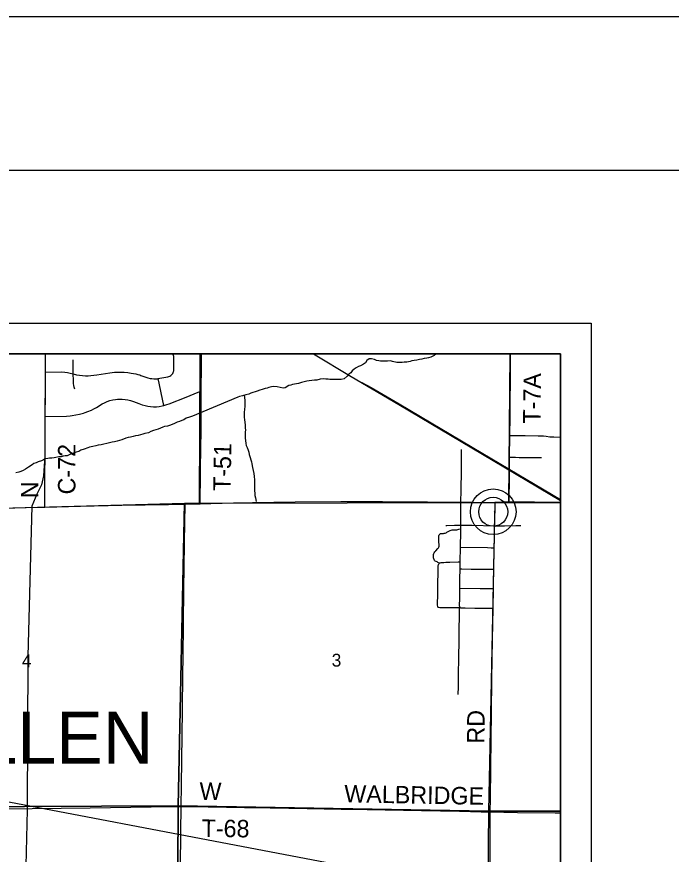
# Model space of a CAD drawing. Extents: x 0 to 34, y 0 to 22.
# Drawn here: x 7.128 to 9.261, y 19.268 to 22 of the extents above; entities that cross this region are included whole.
import ezdxf

# ---------------------------------------------------------------- set-up
doc = ezdxf.new("R2010")
doc.units = 0
for name, color, linetype in [('Default', 7, 'Continuous'), ('GM_X_County_Road', 7, 'Continuous'), ('GM_X_County_Road_Text', 7, 'Continuous'), ('GM_X_Interstate_Route', 7, 'Continuous'), ('GM_X_Major_River', 7, 'Continuous'), ('GM_X_Minor_River', 7, 'Continuous'), ('GM_X_Rail_Line', 7, 'Continuous'), ('GM_X_Section', 7, 'Continuous'), ('GM_X_Section_Text', 7, 'Continuous'), ('GM_X_State_Route', 7, 'Continuous'), ('GM_X_Township_Road', 7, 'Continuous'), ('GM_X_Township_Road_Text', 7, 'Continuous'), ('GM_X_Township_Text', 7, 'Continuous'), ('GM_X_Unincorporated', 7, 'Continuous'), ('GM_X_Unincorporated_Location', 7, 'Continuous'), ('SH_Border', 7, 'Continuous'), ('SH_Cut_Line', 7, 'Continuous'), ('SH_Data', 7, 'Continuous'), ('SH_Text', 7, 'Continuous')]:
    doc.layers.add(name, color=color, linetype=linetype)

msp = doc.modelspace()

# ---------------------------------------------------------------- linework, layer by layer
at = {"layer": 'Default'}
for points in [[(7.7257, 20.9), (6.7117, 20.9), (6.7136, 20.3867), (7.6743, 20.413), (7.7236, 20.4137)], [(8.7361, 20.9), (7.7257, 20.9), (7.7236, 20.4137), (8.6867, 20.4157), (8.7314, 20.4172)], [(8.9, 20.4157), (8.9, 20.9), (8.7361, 20.9), (8.7314, 20.4172)], [(8.9, 19.4085), (8.9, 20.4157), (8.7314, 20.4172), (8.6867, 20.4157), (8.666, 19.4088)], [(8.9, 18.3933), (8.9, 19.4085), (8.666, 19.4088), (8.6554, 18.3927)]]:
    msp.add_lwpolyline(points, close=True, dxfattribs=at)
at = {"layer": 'GM_X_County_Road'}
msp.add_line((7.2211, 20.8407), (7.2213, 20.9), dxfattribs=at)
for points in [[(7.2206, 20.6963), (7.221, 20.8181), (7.2211, 20.8407)], [(7.2196, 20.4008), (7.2195, 20.4853), (7.22, 20.5881), (7.2205, 20.6534), (7.2206, 20.6963)], [(7.6641, 19.424), (7.665, 19.4929), (7.668, 19.7384), (7.6697, 19.8566), (7.6702, 19.9094), (7.6728, 20.1332), (7.6756, 20.3539), (7.6766, 20.4036), (7.6767, 20.4104)], [(6.9678, 19.4166), (6.9849, 19.4166), (7.1776, 19.4172), (7.3674, 19.4198), (7.5661, 19.4229), (7.5971, 19.4234), (7.6537, 19.424), (7.6641, 19.424)], [(7.6615, 19.1928), (7.6618, 19.2257), (7.663, 19.3406), (7.6641, 19.424)]]:
    msp.add_lwpolyline(points, dxfattribs=at)
at = {"layer": 'GM_X_Interstate_Route'}
msp.add_lwpolyline([(8.9, 17.3895), (8.9, 20.9), (4.7088, 20.9), (4.7053, 20.5025), (4.7052, 20.3461), (4.7052, 20.3382), (4.7052, 20.2636), (4.7052, 20.2455), (4.7051, 20.2077), (4.7051, 20.1455), (4.7053, 20.0088), (4.7051, 19.9497), (4.7052, 19.9217), (4.7054, 19.8814), (4.7049, 19.8162), (4.7051, 19.726), (4.7054, 19.4463), (4.7058, 19.4215), (4.706, 19.4081), (4.7064, 19.3593), (4.7066, 19.3437), (4.7069, 19.3065), (4.7068, 19.2692), (4.7066, 19.2071)], dxfattribs=at)
at = {"layer": 'GM_X_Major_River'}
for points in [[(8.4955, 20.9), (8.4953, 20.8999), (8.4884, 20.8954), (8.4778, 20.8893), (8.4702, 20.8871), (8.4641, 20.8864), (8.4554, 20.8853), (8.4482, 20.8834), (8.4406, 20.8819), (8.4315, 20.8797), (8.4235, 20.8782), (8.416, 20.8771), (8.4099, 20.8756), (8.3996, 20.8734), (8.3906, 20.8731), (8.3845, 20.8727), (8.375, 20.8724), (8.3663, 20.8721), (8.3531, 20.8756), (8.3459, 20.8771), (8.3368, 20.8768), (8.3269, 20.8761), (8.3201, 20.8761), (8.314, 20.8765), (8.308, 20.8773), (8.3008, 20.8792), (8.2936, 20.8819), (8.2841, 20.8839), (8.2762, 20.8839), (8.269, 20.8782), (8.2644, 20.8714), (8.2583, 20.8669), (8.248, 20.8613), (8.2416, 20.8587), (8.234, 20.8545), (8.2275, 20.8508), (8.221, 20.8447), (8.2168, 20.8387), (8.2108, 20.8345), (8.2047, 20.8274), (8.1952, 20.8194), (8.1849, 20.8172), (8.1766, 20.8165), (8.1701, 20.8165), (8.1637, 20.8169), (8.1489, 20.817), (8.1429, 20.8174), (8.1353, 20.8178), (8.1281, 20.8186), (8.1167, 20.8175), (8.1061, 20.8149), (8.0985, 20.8146), (8.0902, 20.8139), (8.0807, 20.8128), (8.0739, 20.8113), (8.0648, 20.8091), (8.0557, 20.8072), (8.0458, 20.8042), (8.0397, 20.8031), (8.0333, 20.8017), (8.0272, 20.8002)], [(8.0272, 20.8002), (8.0208, 20.7983), (8.0147, 20.7968), (8.0033, 20.79), (7.9965, 20.7889), (7.9866, 20.7905), (7.9764, 20.7928), (7.9662, 20.794), (7.9582, 20.7929), (7.9499, 20.7907), (7.9438, 20.7888), (7.9374, 20.787), (7.9279, 20.784), (7.9207, 20.7817), (7.9115, 20.7784), (7.9051, 20.7761), (7.8975, 20.7739), (7.8907, 20.7716), (7.8846, 20.7694), (7.8744, 20.7664), (7.8641, 20.7638), (7.8539, 20.7608), (7.8482, 20.7593)], [(7.8482, 20.7593), (7.7012, 20.6971), (7.6906, 20.6941), (7.6804, 20.6904), (7.6724, 20.6851), (7.6663, 20.6832), (7.6583, 20.6798), (7.6511, 20.6776), (7.6397, 20.6716), (7.6257, 20.6663), (7.6192, 20.6645), (7.6098, 20.663), (7.6037, 20.6611), (7.5961, 20.6578), (7.5885, 20.6548), (7.5809, 20.6522), (7.5741, 20.6503), (7.5646, 20.6469), (7.557, 20.6432), (7.5456, 20.6402), (7.5384, 20.6379), (7.5312, 20.6361), (7.5232, 20.6342), (7.5149, 20.6331), (7.5073, 20.6313), (7.499, 20.629), (7.4914, 20.6272), (7.4834, 20.6249), (7.4709, 20.6201), (7.4553, 20.616), (7.4466, 20.6134), (7.439, 20.6119), (7.4219, 20.6082), (7.4113, 20.606), (7.4026, 20.6041), (7.3931, 20.6023), (7.3859, 20.6008), (7.3757, 20.5985), (7.3654, 20.5959), (7.3593, 20.5941), (7.3472, 20.5896), (7.3366, 20.5858), (7.3301, 20.5821), (7.321, 20.5795), (7.313, 20.5769), (7.3005, 20.572), (7.2925, 20.5682), (7.2861, 20.5675), (7.2793, 20.5664), (7.2721, 20.5649), (7.2649, 20.5642), (7.2554, 20.5623), (7.2493, 20.5616), (7.2417, 20.5605), (7.2349, 20.5598), (7.2288, 20.5594), (7.2209, 20.5583), (7.2148, 20.555), (7.208, 20.5516), (7.1981, 20.5478), (7.1909, 20.5452), (7.184, 20.5422), (7.1776, 20.5381)], [(7.1776, 20.5381), (7.1666, 20.5302), (7.1567, 20.5245), (7.1483, 20.5204), (7.1411, 20.5162), (7.135, 20.5144), (7.1248, 20.5122)]]:
    msp.add_lwpolyline(points, dxfattribs=at)
at = {"layer": 'GM_X_Minor_River'}
msp.add_lwpolyline([(7.8695, 20.7652), (7.8709, 20.7493), (7.8708, 20.7425), (7.8715, 20.7342), (7.8715, 20.7281), (7.8703, 20.7198), (7.8695, 20.7091), (7.8691, 20.7019), (7.8691, 20.694), (7.8702, 20.6856), (7.8709, 20.678), (7.8723, 20.6681), (7.8727, 20.6594), (7.873, 20.6518), (7.8726, 20.6458), (7.8722, 20.6386), (7.8725, 20.6317), (7.8725, 20.6249), (7.8732, 20.6173), (7.8743, 20.6082), (7.8758, 20.6017), (7.8788, 20.5945), (7.8822, 20.5858), (7.884, 20.5793), (7.8859, 20.5725), (7.8889, 20.5622), (7.8907, 20.5546), (7.8926, 20.5482), (7.8941, 20.5413), (7.8967, 20.5295), (7.8989, 20.52), (7.9007, 20.5102), (7.9018, 20.4999), (7.9025, 20.4889), (7.9025, 20.4821), (7.9028, 20.4756), (7.9024, 20.4688), (7.9024, 20.4612), (7.9027, 20.454), (7.9034, 20.4457), (7.9042, 20.4388), (7.9056, 20.4312), (7.9086, 20.4191)], dxfattribs=at)
at = {"layer": 'GM_X_Rail_Line'}
for points in [[(7.2205, 20.9), (7.2191, 20.567), (7.2148, 20.5028), (7.2089, 20.4736), (7.1929, 20.443), (7.1768, 20.4036), (7.1637, 19.9147), (7.1622, 19.4128), (7.1374, 18.4088), (7.1389, 18.0601), (7.1325, 17.6042)], [(8.0952, 20.9), (8.2181, 20.8268), (8.373, 20.7348), (8.6459, 20.5729), (8.9, 20.4221)], [(8.2524, 20.8064), (8.283, 20.791), (8.3742, 20.7368), (8.6471, 20.5749), (8.9, 20.4248)]]:
    msp.add_lwpolyline(points, dxfattribs=at)
at = {"layer": 'GM_X_Section'}
for points in [[(7.6743, 20.413), (7.6545, 19.4258), (6.6525, 19.4215), (6.6624, 20.3857), (6.7136, 20.3867)], [(7.7236, 20.4137), (8.6867, 20.4157), (8.666, 19.4088), (7.6545, 19.4258), (7.6743, 20.413)], [(7.6545, 19.4258), (7.6481, 18.4165), (6.6382, 18.4059), (6.6525, 19.4215)], [(8.666, 19.4088), (8.6554, 18.3927), (7.6481, 18.4165), (7.6545, 19.4258)]]:
    msp.add_lwpolyline(points, close=True, dxfattribs=at)
at = {"layer": 'GM_X_State_Route'}
for points in [[(7.0328, 20.3951), (7.0479, 20.3956), (7.159, 20.399), (7.2196, 20.4008), (7.3361, 20.4034), (7.4704, 20.4063), (7.6226, 20.4091), (7.6767, 20.4104), (7.7258, 20.4115)], [(7.7258, 20.4115), (7.7606, 20.4123), (7.8345, 20.4139), (7.8965, 20.4153), (8.0358, 20.4178), (8.1841, 20.4186), (8.2528, 20.4184)], [(8.2528, 20.4184), (8.2608, 20.4184), (8.3198, 20.4182), (8.4669, 20.4173), (8.5758, 20.4165), (8.6148, 20.4166), (8.6879, 20.416)], [(8.6879, 20.416), (8.7102, 20.4159), (8.7328, 20.4156)], [(8.7328, 20.4156), (8.7713, 20.4151), (8.9, 20.4145)]]:
    msp.add_lwpolyline(points, dxfattribs=at)
at = {"layer": 'GM_X_Township_Road'}
for p, q in [((7.3122, 20.835), (7.3122, 20.8809)), ((7.6071, 20.7317), (7.589, 20.8195)), ((8.5758, 20.4165), (8.5761, 20.4554)), ((8.5753, 20.33), (8.5754, 20.3416)), ((8.5735, 20.2217), (8.5743, 20.2697)), ((8.683, 20.1977), (8.6845, 20.2677)), ((8.5731, 20.1986), (8.5735, 20.2217)), ((8.5718, 20.1013), (8.5721, 20.1361)), ((8.6807, 20.0705), (8.6817, 20.1347))]:
    msp.add_line(p, q, dxfattribs=at)
for points in [[(7.589, 20.8195), (7.5946, 20.8206), (7.6208, 20.8258), (7.624, 20.8265), (7.6271, 20.8278), (7.6297, 20.8294), (7.6322, 20.8315), (7.6344, 20.8338), (7.6363, 20.8364), (7.6379, 20.8392), (7.6391, 20.8423), (7.6398, 20.8454), (7.6402, 20.8485), (7.6403, 20.886), (7.6401, 20.8889), (7.6397, 20.8922), (7.6389, 20.8953), (7.6379, 20.8984), (7.6372, 20.9)], [(7.7291, 20.7774), (7.7293, 20.7941), (7.7299, 20.8492), (7.7303, 20.9)], [(8.7351, 20.634), (8.7361, 20.6948), (8.736, 20.6988), (8.7375, 20.8581), (8.7376, 20.9)], [(7.2211, 20.8407), (7.2747, 20.8413), (7.2842, 20.8407), (7.2933, 20.8393), (7.3023, 20.8377), (7.3122, 20.835)], [(7.3122, 20.835), (7.3231, 20.8324), (7.3325, 20.8305), (7.3419, 20.8293), (7.3514, 20.8287), (7.3606, 20.8288), (7.3696, 20.8295), (7.3885, 20.8322), (7.4314, 20.8388), (7.4462, 20.8403), (7.4558, 20.8408), (7.4682, 20.8407), (7.4779, 20.8404), (7.4897, 20.8395), (7.5003, 20.8379), (7.5084, 20.8365), (7.516, 20.8349), (7.5228, 20.8332), (7.5285, 20.8315), (7.5324, 20.8302), (7.5556, 20.8222), (7.5622, 20.8205), (7.5678, 20.8195), (7.5747, 20.8188), (7.581, 20.8187), (7.5864, 20.8191), (7.589, 20.8195)], [(7.3169, 20.7854), (7.3152, 20.7914), (7.3139, 20.7976), (7.3131, 20.8038), (7.3127, 20.8132), (7.3122, 20.835)], [(7.6071, 20.7317), (7.6168, 20.7347), (7.6252, 20.7378), (7.68, 20.7596), (7.7191, 20.7753), (7.7221, 20.7764), (7.7243, 20.7769), (7.7267, 20.7772), (7.7291, 20.7774)], [(7.7258, 20.4115), (7.7267, 20.5111), (7.7283, 20.6044), (7.7288, 20.6383), (7.7285, 20.7068), (7.7291, 20.7774)], [(7.2206, 20.6963), (7.2899, 20.6975), (7.3023, 20.6982), (7.3085, 20.699), (7.3207, 20.701), (7.3329, 20.7036), (7.3449, 20.7067), (7.3508, 20.7087), (7.3595, 20.7119), (7.371, 20.7168), (7.3793, 20.7209), (7.3875, 20.7254), (7.406, 20.7368), (7.4143, 20.7411), (7.4228, 20.7448), (7.4316, 20.7478), (7.4407, 20.7501), (7.4498, 20.7518), (7.456, 20.7525), (7.4622, 20.7527), (7.4716, 20.7526), (7.4808, 20.7518), (7.49, 20.7502), (7.4991, 20.748), (7.5079, 20.745), (7.5253, 20.7383), (7.537, 20.7341), (7.5459, 20.7315), (7.5551, 20.7296), (7.5643, 20.7285), (7.5736, 20.7279), (7.5829, 20.728), (7.5922, 20.7289), (7.6014, 20.7304), (7.6071, 20.7317)], [(8.7344, 20.5634), (8.7345, 20.594), (8.7351, 20.634)], [(8.7351, 20.634), (8.7601, 20.6336), (8.7851, 20.6337), (8.8273, 20.6333), (8.8445, 20.6325)], [(8.8445, 20.6325), (8.8538, 20.6314), (8.8659, 20.6299), (8.8791, 20.6295), (8.9, 20.6288)], [(8.5761, 20.4554), (8.5773, 20.5204), (8.578, 20.5637), (8.5781, 20.5885)], [(8.7328, 20.4156), (8.7329, 20.4209), (8.733, 20.4335), (8.7336, 20.4821), (8.7344, 20.5444), (8.7344, 20.5634)], [(8.7344, 20.5634), (8.7535, 20.563), (8.7658, 20.5628), (8.8385, 20.5624)], [(8.5755, 20.3666), (8.5756, 20.3734), (8.5758, 20.4098), (8.5758, 20.4154), (8.5758, 20.4165)], [(8.6857, 20.3399), (8.6861, 20.3534), (8.6863, 20.3616), (8.6874, 20.3996), (8.6878, 20.4126), (8.6879, 20.416)], [(8.6879, 20.416), (8.7102, 20.4159), (8.7328, 20.4156)], [(8.5754, 20.3416), (8.5754, 20.3489), (8.5755, 20.3666)], [(8.5055, 20.2178), (8.5009, 20.2202), (8.4981, 20.2217), (8.4951, 20.223), (8.4921, 20.2245), (8.4899, 20.2266), (8.4881, 20.2291), (8.487, 20.2318), (8.4864, 20.235), (8.486, 20.2387), (8.4861, 20.2426), (8.4864, 20.2456), (8.4875, 20.2489), (8.4887, 20.2516), (8.4903, 20.2541), (8.492, 20.2558), (8.494, 20.2582), (8.5006, 20.2649), (8.5023, 20.2674), (8.5035, 20.2701), (8.5043, 20.273), (8.5046, 20.2761), (8.5045, 20.2792), (8.504, 20.2853), (8.5037, 20.2915), (8.5037, 20.304), (8.504, 20.3072), (8.5048, 20.3102), (8.5066, 20.3126), (8.5092, 20.314), (8.5122, 20.3145), (8.5184, 20.3147), (8.5215, 20.315), (8.5245, 20.3157), (8.5274, 20.3168), (8.5302, 20.3182), (8.5382, 20.3231), (8.541, 20.3244), (8.544, 20.3254), (8.547, 20.326), (8.5501, 20.3263), (8.5595, 20.3266), (8.5626, 20.3268), (8.5657, 20.3273), (8.5687, 20.3282), (8.5753, 20.33)], [(8.5267, 20.3407), (8.5299, 20.3408), (8.5547, 20.341), (8.5754, 20.3416)], [(8.5743, 20.2697), (8.5752, 20.3211), (8.5753, 20.33)], [(8.5754, 20.3416), (8.5842, 20.3418), (8.5939, 20.3418), (8.6125, 20.3411), (8.6857, 20.3399)], [(8.6845, 20.2677), (8.6851, 20.2949), (8.6857, 20.3399)], [(8.6857, 20.3399), (8.7182, 20.3398), (8.7552, 20.3401), (8.7707, 20.3401)], [(8.5743, 20.2697), (8.662, 20.2682), (8.6747, 20.2679), (8.6845, 20.2677)], [(8.5731, 20.0735), (8.5704, 20.0726), (8.5678, 20.072), (8.5652, 20.0716), (8.5627, 20.0714), (8.5336, 20.0719), (8.5272, 20.0719), (8.5221, 20.0719), (8.5133, 20.072), (8.5102, 20.0721), (8.507, 20.0722), (8.5023, 20.0728), (8.5007, 20.0741), (8.5001, 20.0758), (8.4997, 20.0806), (8.4997, 20.084), (8.4998, 20.0925), (8.5002, 20.107), (8.5005, 20.1224), (8.5007, 20.1383), (8.5009, 20.1504), (8.5016, 20.1877), (8.5017, 20.2095), (8.5022, 20.2126), (8.5033, 20.2155), (8.5055, 20.2178)], [(8.5055, 20.2178), (8.5081, 20.2189), (8.5112, 20.2194), (8.5205, 20.2203), (8.5267, 20.2207), (8.5391, 20.2211), (8.5666, 20.2216), (8.5735, 20.2217)], [(8.5721, 20.1361), (8.5725, 20.1652), (8.5731, 20.1986)], [(8.5731, 20.1986), (8.5785, 20.1986), (8.6096, 20.1984), (8.659, 20.1981), (8.683, 20.1977)], [(8.6817, 20.1347), (8.6819, 20.1458), (8.683, 20.1977)], [(8.5721, 20.1361), (8.6382, 20.1353), (8.6484, 20.1352), (8.6718, 20.1349), (8.6817, 20.1347)], [(8.5731, 20.0735), (8.5725, 20.0742), (8.5721, 20.0749), (8.5718, 20.0758), (8.5717, 20.0765), (8.5716, 20.0776), (8.5716, 20.0804), (8.5718, 20.1013)], [(8.5671, 19.7896), (8.5674, 19.8146), (8.5681, 19.852), (8.5688, 19.9114), (8.5695, 19.9645), (8.57, 20.002), (8.5703, 20.0176), (8.5706, 20.03), (8.5708, 20.0425), (8.5708, 20.0614), (8.5708, 20.0667), (8.5709, 20.0687), (8.571, 20.0703), (8.5713, 20.0711), (8.5718, 20.0718), (8.5722, 20.0724), (8.5731, 20.0735)], [(8.5731, 20.0735), (8.5736, 20.073), (8.5747, 20.0723), (8.5759, 20.0718), (8.5772, 20.0717), (8.5783, 20.0715), (8.5797, 20.0715), (8.5832, 20.0714), (8.59, 20.0714), (8.6207, 20.0711), (8.6807, 20.0705)], [(8.6714, 19.4059), (8.6717, 19.4495), (8.6745, 19.6454), (8.6752, 19.7293), (8.6769, 19.8381), (8.6779, 19.9034), (8.6791, 19.9686), (8.6807, 20.0705)], [(7.6641, 19.424), (7.673, 19.4241), (7.7518, 19.4231), (7.8697, 19.4208), (7.9536, 19.4193), (8.0745, 19.4171), (8.1856, 19.4153), (8.2699, 19.4138), (8.4468, 19.4105), (8.5713, 19.4086), (8.642, 19.4063), (8.6714, 19.4059)], [(8.6602, 18.3934), (8.6612, 18.4674), (8.6614, 18.5078), (8.6617, 18.5264), (8.6623, 18.6041), (8.6659, 18.8932), (8.667, 18.9864), (8.6678, 19.0517), (8.6695, 19.1604), (8.671, 19.2972), (8.6712, 19.3936), (8.6714, 19.4059)], [(8.6714, 19.4059), (8.7602, 19.4046), (8.8825, 19.4031), (8.9, 19.403)]]:
    msp.add_lwpolyline(points, dxfattribs=at)
at = {"layer": 'GM_X_Unincorporated'}
for radius in [0.0744, 0.0472]:
    msp.add_circle((8.6809, 20.3852), radius, dxfattribs=at)
at = {"layer": 'GM_X_Unincorporated_Location'}
msp.add_line((8.6809, 20.3852), (8.6809, 20.3852), dxfattribs=at)
at = {"layer": 'SH_Border'}
msp.add_lwpolyline([(1.5, 21.5), (33.5, 21.5), (33.5, 0.5), (1.5, 0.5)], close=True, dxfattribs=at)
at = {"layer": 'SH_Cut_Line'}
msp.add_lwpolyline([(0, 0), (34, 0), (34, 22), (0, 22)], close=True, dxfattribs=at)
at = {"layer": 'SH_Data'}
for p, q in [((2, 21), (9, 21)), ((9, 21), (9, 14)), ((2.1, 20.9), (8.9, 20.9)), ((8.9, 20.9), (8.9, 14.1))]:
    msp.add_line(p, q, dxfattribs=at)
at = {"layer": 'SH_Text'}
msp.add_lwpolyline([(9.2181, 19.0346), (2.1904, 20.3744), (9.2181, 18.3428)], close=True, dxfattribs=at)

# ---------------------------------------------------------------- texts
at = {"layer": 'GM_X_County_Road_Text'}
for s, height, p in [('C-72', 0.05682, (7.3191, 20.4418)), ('N', 0.0568, (7.1981, 20.4293))]:
    msp.add_text(s, height=height, rotation=90, dxfattribs=at).set_placement(p)
at = {"layer": 'GM_X_Section_Text'}
for s, p in [('4', (7.1446, 19.878)), ('3', (8.1546, 19.8802))]:
    msp.add_text(s, height=0.0419, rotation=0, dxfattribs=at).set_placement(p)
at = {"layer": 'GM_X_Township_Road_Text'}
for s, height, rotation, p in [('T-7A', 0.05682, 89.3637, (8.835, 20.6725)), ('T-51', 0.05682, 88.9397, (7.8249, 20.4525)), ('RD', 0.05682, 89.5063, (8.6522, 19.6287)), ('W', 0.0568, 359.2752, (7.7232, 19.4458)), ('WALBRIDGE', 0.05682, 358.9712, (8.195, 19.4375)), ('T-68', 0.05682, 359.2931, (7.73, 19.3249))]:
    msp.add_text(s, height=height, rotation=rotation, dxfattribs=at).set_placement(p)
at = {"layer": 'GM_X_Township_Text'}
msp.add_text('ALLEN', height=0.17045, rotation=0, dxfattribs=at).set_placement((6.8508, 19.5631))

doc.saveas('drawing.dxf')
